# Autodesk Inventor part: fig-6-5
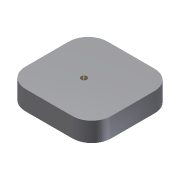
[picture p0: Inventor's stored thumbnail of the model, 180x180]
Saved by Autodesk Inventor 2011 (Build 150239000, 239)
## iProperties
Created: 2004-05
Part Number: fig-6-5
Document SubType Name: Modeling
Designer: CADCIM Technologies
Manufacturer: Standard
Standards Organization: Custom
Density: 1 g/cm^3
Author: CADCIM Technologies
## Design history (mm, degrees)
sketch "Sketch1"
  geometry: L1 (0, 0)-(44.293, 0); L2 (44.293, 0)-(44.293, 42.442); L3 (44.293, 42.442)-(0, 42.442); L4 (0, 42.442)-(0, 0)
  constraints: 8 end point, 2 parallel, 1 horizontal, 1 perpendicular
extrude "Extrusion1" new body sketch "Sketch1" distance "d0" = 10; taper "d1" = 0 deg
fillet "Fillet1" dims "d2" = 10
sketch "Sketch2"
  geometry: 1 further point
sketch "Sketch3"
  geometry: L1 (10, 42.442)-(34.293, 42.442) reference; L2 (0, 10)-(0, 32.442) reference; L3 (34.293, 0)-(10, 0) reference; L4 (44.293, 32.442)-(44.293, 10) reference; A1 r 10 centre (34.293, 32.442) between (44.293, 32.442) and (34.293, 42.442) reference; A2 r 10 centre (10, 32.442) between (10, 42.442) and (0, 32.442) reference; A3 r 10 centre (10, 10) between (0, 10) and (10, 0) reference; A4 r 10 centre (34.293, 10) between (34.293, 0) and (44.293, 10) reference; 1 further point
workaxis "Work Axis1"
  workpoint "Work Point1"
hole "Hole3" diameter "d24" = 3; stored, may be unused: countersink angle "d28" = 90 deg, drill point angle "d30" = 118 deg; dims "d22" = 10, "d23" = 10, "d25" = 6, "d26" = 4, "d27" = 2, "d29" = 8
body "Solid1"
